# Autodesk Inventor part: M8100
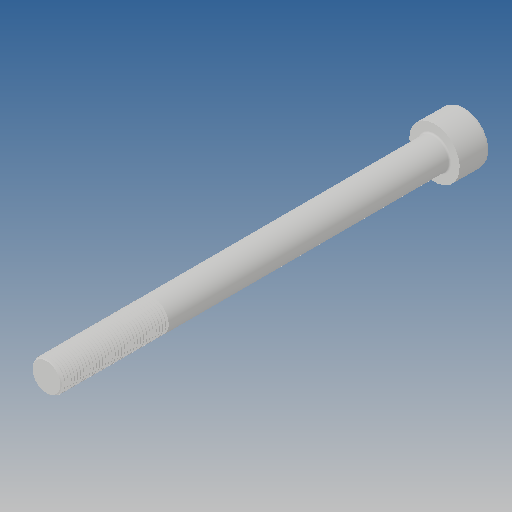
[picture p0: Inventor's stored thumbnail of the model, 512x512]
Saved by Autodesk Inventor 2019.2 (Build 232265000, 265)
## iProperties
Created: 2013-07
Part Number: M8100
Material: Ogólny
Document SubType Name: Modeling
Designer: CADENGINEERING4
Density: 1 g/cm^3
Appearance: Domyślna
Author: CADENGINEERING4
Revision Number: ÈÎºÎ
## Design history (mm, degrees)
feature "gb70M8x100_GB_FASTENER_SCREWS_HSHCS M8X80-N-1-solid1"
node "Bryła1"
